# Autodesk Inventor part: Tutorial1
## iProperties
Shininess: 64.0
Length Units: 11269
Angle Units: 11279
Time Units: 11290
Mass Units: 11283
Length Display Precision: 3
Angle Display Precision: 2
Compacted: True
Part Number: Tutorial1
Document SubType Name: Modeling
Created: 2002-11
Designer: deepak
Density: 0.0
Volumn: 0.0
Area: 0.0
PropertySet Name: Model Information
Control State: 0
Master: False
Checked Out: False
Author: deepak
